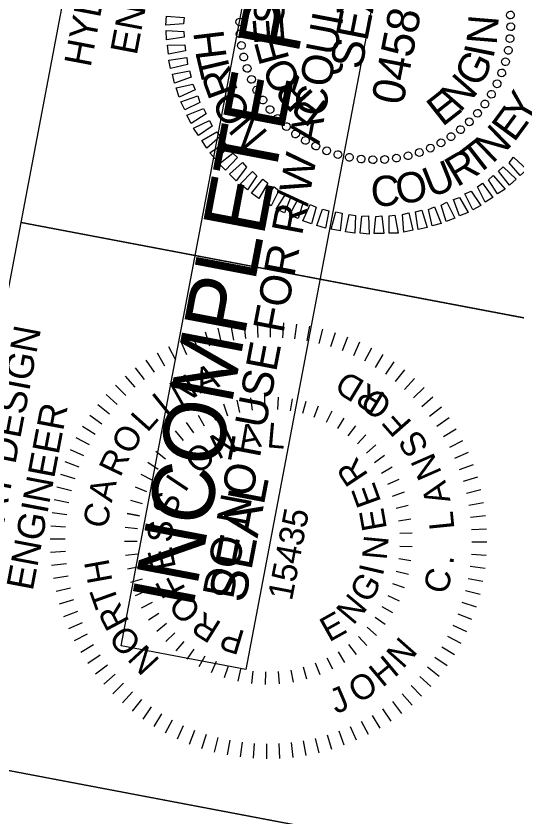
# Model space of a CAD drawing. Extents: x 1615685 to 1617075, y 899072 to 901363.
# Drawn here: x 1616035.7 to 1616128.3, y 900930.9 to 901079 of the extents above; entities that cross this region are included whole.
import ezdxf

# ---------------------------------------------------------------- set-up
doc = ezdxf.new("R2010")
doc.units = 0
for name, color, linetype in [('Default', 7, 'Continuous'), ('Exist Structure Minor Pipes RCP 15 Inch Text', 7, 'Continuous'), ('Prop Plan Preparation Crest Label', 7, 'Continuous'), ('Scratch_Level_8', 7, 'Continuous')]:
    doc.layers.add(name, color=color, linetype=linetype)

msp = doc.modelspace()

# ---------------------------------------------------------------- linework, layer by layer
at = {"layer": 'Default'}
for p, q in [((1616077.12, 901077.93), (1616077.12, 901077.93)), ((1616127.23, 901077.04), (1616127.23, 901077.04)), ((1616077.15, 901075.73), (1616077.15, 901075.73)), ((1616127.05, 901074.83), (1616127.05, 901074.83)), ((1616077.39, 901073.55), (1616077.39, 901073.55)), ((1616126.78, 901072.64), (1616126.78, 901072.64)), ((1616077.85, 901071.47), (1616077.85, 901071.47)), ((1616078.46, 901069.37), (1616078.46, 901069.37)), ((1616126.27, 901070.55), (1616126.27, 901070.55)), ((1616125.56, 901068.5), (1616125.56, 901068.5)), ((1616079.29, 901067.32), (1616079.29, 901067.32)), ((1616124.71, 901066.47), (1616124.71, 901066.47)), ((1616080.17, 901065.32), (1616080.17, 901065.32)), ((1616081.38, 901063.45), (1616081.38, 901063.45)), ((1616123.67, 901064.53), (1616123.67, 901064.53)), ((1616122.46, 901062.73), (1616122.46, 901062.73)), ((1616082.62, 901061.68), (1616082.62, 901061.68)), ((1616121.1, 901061.01), (1616121.1, 901061.01)), ((1616084.14, 901060.06), (1616084.14, 901060.06)), ((1616119.57, 901059.43), (1616119.57, 901059.43)), ((1616085.72, 901058.53), (1616085.72, 901058.53)), ((1616117.96, 901057.96), (1616117.96, 901057.96)), ((1616087.45, 901057.17), (1616087.45, 901057.17)), ((1616089.25, 901055.96), (1616089.25, 901055.96)), ((1616116.18, 901056.67), (1616116.18, 901056.67)), ((1616091.13, 901054.93), (1616091.13, 901054.93)), ((1616112.37, 901054.61), (1616112.37, 901054.61)), ((1616114.32, 901055.51), (1616114.32, 901055.51)), ((1616093.16, 901054.08), (1616093.16, 901054.08)), ((1616095.21, 901053.37), (1616095.21, 901053.37)), ((1616108.22, 901053.18), (1616108.22, 901053.18)), ((1616110.32, 901053.79), (1616110.32, 901053.79)), ((1616097.35, 901052.85), (1616097.35, 901052.85)), ((1616099.54, 901052.58), (1616099.54, 901052.58)), ((1616101.71, 901052.46), (1616101.71, 901052.46)), ((1616103.9, 901052.49), (1616103.9, 901052.49)), ((1616106.09, 901052.73), (1616106.09, 901052.73))]:
    msp.add_line(p, q, dxfattribs=at)
for points in [[(1616066.66, 901077.57), (1616063.41, 901077.34), (1616063.53, 901079), (1616066.79, 901078.77)], [(1616066.79, 901075.1), (1616063.49, 901074.63), (1616063.47, 901076.36), (1616066.75, 901076.18)], [(1616067.02, 901072.61), (1616063.9, 901072), (1616063.7, 901073.62), (1616066.88, 901073.71)], [(1616067.4, 901070.1), (1616064.29, 901069.33), (1616063.98, 901070.86), (1616067.28, 901071.34)], [(1616068.06, 901067.73), (1616064.99, 901066.64), (1616064.6, 901068.3), (1616067.78, 901068.9)], [(1616068.82, 901065.39), (1616065.86, 901064.03), (1616065.33, 901065.76), (1616068.42, 901066.43)], [(1616069.69, 901063.03), (1616066.88, 901061.69), (1616066.15, 901063.16), (1616069.32, 901064.27)], [(1616070.86, 901060.92), (1616068.07, 901059.17), (1616067.3, 901060.69), (1616070.34, 901061.93)], [(1616071.99, 901058.66), (1616069.46, 901056.91), (1616068.52, 901058.31), (1616071.49, 901059.72)], [(1616073.46, 901056.74), (1616071, 901054.62), (1616070.06, 901056.03), (1616072.81, 901057.63)], [(1616075, 901054.71), (1616072.62, 901052.47), (1616071.55, 901053.75), (1616074.25, 901055.57)], [(1616076.62, 901052.86), (1616074.44, 901050.54), (1616073.24, 901051.69), (1616075.81, 901053.68)], [(1616078.31, 901051.06), (1616076.4, 901048.58), (1616075.16, 901049.79), (1616077.57, 901051.97)], [(1616127.67, 901052.91), (1616130.14, 901050.64), (1616128.91, 901049.56), (1616126.86, 901051.89)], [(1616080.24, 901049.46), (1616078.47, 901046.9), (1616077.14, 901047.92), (1616079.43, 901050.28)], [(1616125.8, 901051.13), (1616128.16, 901048.89), (1616126.92, 901047.75), (1616124.93, 901050.33)], [(1616082.28, 901048.15), (1616080.6, 901045.31), (1616079.26, 901046.29), (1616081.34, 901048.84)], [(1616123.91, 901049.56), (1616126.12, 901047.04), (1616124.73, 901046.14), (1616123.09, 901048.75)], [(1616084.3, 901046.78), (1616082.88, 901043.9), (1616081.51, 901044.73), (1616083.42, 901047.47)], [(1616121.95, 901048.11), (1616123.89, 901045.49), (1616122.44, 901044.6), (1616121, 901047.43)], [(1616086.51, 901045.59), (1616085.33, 901042.66), (1616083.83, 901043.31), (1616085.6, 901046.12)], [(1616119.83, 901046.64), (1616121.66, 901043.99), (1616120.18, 901043.21), (1616118.71, 901046.14)], [(1616088.81, 901044.58), (1616087.87, 901041.56), (1616086.26, 901042.18), (1616087.79, 901045.09)], [(1616091.19, 901043.71), (1616090.33, 901040.62), (1616088.7, 901041.14), (1616090.06, 901044.19)], [(1616115.36, 901044.61), (1616116.82, 901041.67), (1616115.22, 901041.02), (1616114.33, 901044.04)], [(1616117.67, 901045.48), (1616119.32, 901042.71), (1616117.72, 901042.11), (1616116.62, 901045.07)], [(1616093.55, 901043), (1616092.93, 901039.81), (1616091.29, 901040.28), (1616092.34, 901043.33)], [(1616096.01, 901042.57), (1616095.64, 901039.33), (1616093.96, 901039.61), (1616094.83, 901042.8)], [(1616108.35, 901042.61), (1616109.1, 901039.41), (1616107.4, 901039.08), (1616107.17, 901042.33)], [(1616110.74, 901043.11), (1616111.7, 901039.92), (1616110.05, 901039.58), (1616109.56, 901042.83)], [(1616113.05, 901043.73), (1616114.29, 901040.69), (1616112.62, 901040.25), (1616111.99, 901043.28)], [(1616098.48, 901042.14), (1616098.35, 901038.9), (1616096.62, 901039.14), (1616097.29, 901042.32)], [(1616100.86, 901042.08), (1616101.01, 901038.69), (1616099.32, 901038.87), (1616099.67, 901042.01)], [(1616103.31, 901042.11), (1616103.69, 901038.83), (1616101.95, 901038.81), (1616102.21, 901041.97)], [(1616105.77, 901042.2), (1616106.35, 901038.87), (1616104.67, 901038.89), (1616104.67, 901042.05)]]:
    msp.add_lwpolyline(points, close=True, dxfattribs=at)
for centre, major_axis in [((1616127.12, 901079.23), (0.718, 0.05)), ((1616077.08, 901077.94), (-0.719, 0.013)), ((1616127.18, 901077.05), (0.719, -0.013)), ((1616077.13, 901075.76), (-0.718, -0.05)), ((1616127.04, 901074.87), (0.715, -0.075)), ((1616077.38, 901073.59), (-0.71, -0.112)), ((1616077.81, 901071.44), (-0.698, -0.174)), ((1616126.72, 901072.71), (0.706, -0.138)), ((1616126.21, 901070.58), (0.691, -0.199)), ((1616078.43, 901069.35), (-0.68, -0.234)), ((1616125.51, 901068.51), (0.671, -0.258)), ((1616079.23, 901067.31), (-0.657, -0.292)), ((1616124.64, 901066.5), (0.646, -0.316)), ((1616080.21, 901065.36), (-0.629, -0.348)), ((1616123.6, 901064.58), (0.616, -0.371)), ((1616081.35, 901063.49), (-0.596, -0.402)), ((1616122.39, 901062.76), (0.582, -0.423)), ((1616082.65, 901061.74), (-0.559, -0.452)), ((1616121.03, 901061.05), (0.543, -0.472)), ((1616084.1, 901060.1), (-0.518, -0.499)), ((1616085.68, 901058.59), (-0.472, -0.543)), ((1616119.52, 901059.47), (0.499, -0.518)), ((1616087.39, 901057.23), (-0.423, -0.582)), ((1616116.13, 901056.72), (0.402, -0.596)), ((1616117.89, 901058.02), (0.452, -0.559)), ((1616089.21, 901056.02), (-0.371, -0.616)), ((1616114.27, 901055.58), (0.348, -0.629)), ((1616091.13, 901054.98), (-0.316, -0.646)), ((1616093.14, 901054.11), (-0.258, -0.671)), ((1616110.27, 901053.8), (0.234, -0.68)), ((1616112.31, 901054.6), (0.292, -0.657)), ((1616095.21, 901053.41), (-0.199, -0.691)), ((1616097.34, 901052.9), (-0.138, -0.706)), ((1616099.5, 901052.58), (-0.075, -0.715)), ((1616101.68, 901052.45), (-0.013, -0.719)), ((1616103.86, 901052.5), (0.05, -0.718)), ((1616106.04, 901052.75), (0.112, -0.71)), ((1616108.18, 901053.18), (0.174, -0.698))]:
    msp.add_ellipse(centre, major_axis=major_axis, ratio=0.999708, dxfattribs=at)
at = {"layer": 'Exist Structure Minor Pipes RCP 15 Inch Text'}
msp.add_lwpolyline([(1616078.19, 900958.16), (1616055.11, 900962.54), (1616082.53, 901106.96), (1616105.61, 901102.58)], close=True, dxfattribs=at)
at = {"layer": 'Prop Plan Preparation Crest Label'}
for p, q in [((1616077.83, 901022.13), (1616078.14, 901019.39)), ((1616080.26, 901022.33), (1616080.4, 901019.58)), ((1616082.7, 901022.38), (1616082.67, 901019.63)), ((1616085.13, 901022.29), (1616084.94, 901019.54)), ((1616087.56, 901022.05), (1616087.2, 901019.32)), ((1616070.67, 901020.65), (1616071.47, 901018.01)), ((1616073.03, 901021.28), (1616073.66, 901018.61)), ((1616075.42, 901021.78), (1616075.89, 901019.07)), ((1616089.97, 901021.66), (1616089.45, 901018.96)), ((1616092.35, 901021.13), (1616091.67, 901018.47)), ((1616094.69, 901020.46), (1616093.85, 901017.84)), ((1616066.1, 901018.95), (1616067.21, 901016.44)), ((1616068.36, 901019.87), (1616069.32, 901017.29)), ((1616096.99, 901019.65), (1616096, 901017.08)), ((1616063.9, 901017.9), (1616065.16, 901015.46)), ((1616099.23, 901018.7), (1616098.09, 901016.2)), ((1616101.42, 901017.61), (1616100.12, 901015.18)), ((1616061.77, 901016.72), (1616063.17, 901014.36)), ((1616103.53, 901016.4), (1616102.09, 901014.05)), ((1616059.71, 901015.41), (1616061.26, 901013.14)), ((1616105.57, 901015.05), (1616103.99, 901012.8)), ((1616057.74, 901013.98), (1616059.41, 901011.81)), ((1616107.52, 901013.6), (1616105.81, 901011.44)), ((1616055.85, 901012.44), (1616057.66, 901010.36)), ((1616109.39, 901012.02), (1616107.54, 901009.98)), ((1616054.06, 901010.78), (1616055.99, 901008.82)), ((1616111.15, 901010.34), (1616109.19, 901008.41)), ((1616052.38, 901009.02), (1616054.42, 901007.18)), ((1616081.62, 901008.61), (1616081.69, 901006.32)), ((1616084.2, 901008.56), (1616084.04, 901006.27)), ((1616112.8, 901008.55), (1616110.73, 901006.74)), ((1616050.8, 901007.16), (1616052.95, 901005.44)), ((1616074.05, 901007.28), (1616074.77, 901005.1)), ((1616076.53, 901007.97), (1616077.03, 901005.73)), ((1616079.06, 901008.41), (1616079.35, 901006.13)), ((1616086.75, 901008.26), (1616086.37, 901006)), ((1616089.26, 901007.72), (1616088.67, 901005.5)), ((1616071.65, 901006.36), (1616072.58, 901004.26)), ((1616090.83, 901004.81), (1616091.63, 901006.96)), ((1616094.07, 901005.92), (1616093.07, 901003.86)), ((1616114.35, 901006.66), (1616112.17, 901004.98)), ((1616049.34, 901005.2), (1616051.59, 901003.62)), ((1616069.35, 901005.21), (1616070.47, 901003.21)), ((1616096.32, 901004.67), (1616095.12, 901002.72)), ((1616115.78, 901004.69), (1616113.5, 901003.14)), ((1616048, 901003.17), (1616050.34, 901001.72)), ((1616067.18, 901003.84), (1616068.49, 901001.96)), ((1616098.44, 901003.22), (1616097.06, 901001.4)), ((1616117.09, 901002.63), (1616114.72, 901001.22)), ((1616065.14, 901002.28), (1616066.63, 901000.53)), ((1616100.41, 901001.58), (1616098.86, 900999.89)), ((1616046.78, 901001.05), (1616049.22, 900999.76)), ((1616063.26, 901000.52), (1616064.91, 900998.92)), ((1616102.22, 900999.74), (1616100.51, 900998.21)), ((1616118.27, 901000.49), (1616115.83, 900999.24)), ((1616045.7, 900998.87), (1616048.2, 900997.72)), ((1616061.57, 900998.58), (1616063.36, 900997.16)), ((1616119.32, 900998.3), (1616116.8, 900997.19)), ((1616103.84, 900997.74), (1616101.99, 900996.39)), ((1616044.75, 900996.62), (1616047.31, 900995.63)), ((1616060.06, 900996.5), (1616061.99, 900995.25)), ((1616105.26, 900995.6), (1616103.28, 900994.43)), ((1616120.24, 900996.04), (1616117.66, 900995.08)), ((1616043.94, 900994.32), (1616046.56, 900993.49)), ((1616058.77, 900994.28), (1616060.81, 900993.22)), ((1616121.02, 900993.72), (1616118.38, 900992.93)), ((1616106.46, 900993.33), (1616104.39, 900992.36)), ((1616043.27, 900991.98), (1616045.93, 900991.3)), ((1616057.7, 900991.94), (1616059.83, 900991.09)), ((1616107.44, 900990.95), (1616105.28, 900990.18)), ((1616121.65, 900991.37), (1616118.97, 900990.73)), ((1616042.73, 900989.6), (1616045.44, 900989.08)), ((1616056.86, 900989.51), (1616059.05, 900988.87)), ((1616108.18, 900988.49), (1616105.96, 900987.93)), ((1616122.15, 900988.98), (1616119.43, 900988.5)), ((1616042.35, 900987.19), (1616045.08, 900986.84)), ((1616056.25, 900987.01), (1616058.5, 900986.58)), ((1616058.5, 900986.58), (1616056.25, 900987.01)), ((1616122.49, 900986.57), (1616119.76, 900986.26)), ((1616108.69, 900985.97), (1616106.42, 900985.63)), ((1616042.11, 900984.76), (1616044.85, 900984.58)), ((1616055.89, 900984.47), (1616058.17, 900984.26)), ((1616108.95, 900983.41), (1616106.66, 900983.29)), ((1616122.69, 900984.14), (1616119.95, 900984)), ((1616042.01, 900982.33), (1616044.77, 900982.31)), ((1616055.78, 900981.9), (1616058.07, 900981.91)), ((1616108.96, 900980.84), (1616106.67, 900980.94)), ((1616122.75, 900981.7), (1616120, 900981.72)), ((1616042.07, 900979.89), (1616044.82, 900980.03)), ((1616055.91, 900979.33), (1616058.19, 900979.56)), ((1616122.65, 900979.26), (1616119.91, 900979.45)), ((1616042.27, 900977.46), (1616045.01, 900977.77)), ((1616108.73, 900978.28), (1616106.46, 900978.61)), ((1616056.29, 900976.79), (1616058.54, 900977.24)), ((1616108.24, 900975.76), (1616106.01, 900976.3)), ((1616122.42, 900976.84), (1616119.69, 900977.19)), ((1616042.62, 900975.05), (1616045.33, 900975.52)), ((1616056.92, 900974.3), (1616059.11, 900974.96)), ((1616122.03, 900974.43), (1616119.33, 900974.95)), ((1616043.12, 900972.66), (1616045.79, 900973.3)), ((1616107.52, 900973.29), (1616105.35, 900974.04)), ((1616057.78, 900971.88), (1616059.91, 900972.75)), ((1616104.47, 900971.85), (1616106.55, 900970.89)), ((1616121.5, 900972.05), (1616118.83, 900972.73)), ((1616043.75, 900970.31), (1616046.38, 900971.1)), ((1616058.88, 900969.55), (1616060.91, 900970.62)), ((1616120.83, 900969.71), (1616118.21, 900970.54)), ((1616044.53, 900967.99), (1616047.11, 900968.95)), ((1616060.19, 900967.34), (1616062.11, 900968.61)), ((1616105.37, 900968.63), (1616103.39, 900969.78)), ((1616103.97, 900966.47), (1616102.11, 900967.81)), ((1616120.01, 900967.41), (1616117.45, 900968.4)), ((1616045.44, 900965.73), (1616047.96, 900966.84)), ((1616061.71, 900965.27), (1616063.49, 900966.71)), ((1616102.37, 900964.46), (1616100.65, 900965.97)), ((1616119.06, 900965.16), (1616116.56, 900966.31)), ((1616046.49, 900963.54), (1616048.94, 900964.79)), ((1616063.42, 900963.35), (1616065.06, 900964.96)), ((1616100.58, 900962.61), (1616099.02, 900964.28)), ((1616117.98, 900962.97), (1616115.55, 900964.27)), ((1616047.68, 900961.4), (1616050.04, 900962.81)), ((1616065.31, 900961.61), (1616066.79, 900963.36)), ((1616098.63, 900960.94), (1616097.23, 900962.76)), ((1616067.36, 900960.05), (1616068.66, 900961.95)), ((1616096.52, 900959.48), (1616095.3, 900961.42)), ((1616116.77, 900960.86), (1616114.42, 900962.31)), ((1616048.98, 900959.34), (1616051.26, 900960.89)), ((1616069.55, 900958.71), (1616070.66, 900960.72)), ((1616071.86, 900957.58), (1616072.77, 900959.68)), ((1616094.28, 900958.21), (1616093.25, 900960.27)), ((1616115.42, 900958.83), (1616113.17, 900960.4)), ((1616050.41, 900957.37), (1616052.59, 900959.05)), ((1616074.27, 900956.68), (1616074.97, 900958.86)), ((1616076.75, 900956.01), (1616077.24, 900958.25)), ((1616089.48, 900956.38), (1616088.87, 900958.58)), ((1616091.92, 900957.18), (1616091.1, 900959.32)), ((1616113.97, 900956.87), (1616111.81, 900958.59)), ((1616051.96, 900955.48), (1616054.03, 900957.29)), ((1616079.29, 900955.59), (1616079.56, 900957.86)), ((1616081.85, 900955.42), (1616081.9, 900957.71)), ((1616084.43, 900955.49), (1616084.25, 900957.77)), ((1616086.98, 900955.81), (1616086.58, 900958.07)), ((1616112.39, 900955.01), (1616110.34, 900956.85)), ((1616053.62, 900953.69), (1616055.58, 900955.62)), ((1616110.7, 900953.25), (1616108.77, 900955.21)), ((1616055.38, 900952.01), (1616057.22, 900954.05)), ((1616057.24, 900950.43), (1616058.95, 900952.59)), ((1616107.03, 900950.04), (1616105.35, 900952.22)), ((1616108.92, 900951.59), (1616107.11, 900953.66)), ((1616059.2, 900948.97), (1616060.77, 900951.23)), ((1616105.05, 900948.62), (1616103.51, 900950.89)), ((1616061.23, 900947.63), (1616062.67, 900949.98)), ((1616103, 900947.31), (1616101.59, 900949.67)), ((1616063.34, 900946.42), (1616064.64, 900948.85)), ((1616065.53, 900945.33), (1616066.67, 900947.83)), ((1616100.86, 900946.13), (1616099.6, 900948.57)), ((1616067.77, 900944.38), (1616068.77, 900946.95)), ((1616096.4, 900944.16), (1616095.45, 900946.74)), ((1616098.66, 900945.08), (1616097.55, 900947.59)), ((1616070.07, 900943.57), (1616070.91, 900946.19)), ((1616072.42, 900942.9), (1616073.09, 900945.56)), ((1616074.8, 900942.37), (1616075.31, 900945.07)), ((1616089.35, 900942.25), (1616088.87, 900944.96)), ((1616091.74, 900942.75), (1616091.1, 900945.42)), ((1616094.09, 900943.38), (1616093.29, 900946.02)), ((1616077.21, 900941.98), (1616077.56, 900944.71)), ((1616079.63, 900941.74), (1616079.82, 900944.48)), ((1616082.07, 900941.65), (1616082.09, 900944.4)), ((1616084.5, 900941.7), (1616084.36, 900944.45)), ((1616086.94, 900941.9), (1616086.63, 900944.64))]:
    msp.add_line(p, q, dxfattribs=at)
at = {"layer": 'Scratch_Level_8'}
msp.add_line((1616036.64, 901040.86), (1616147.13, 901019.89), dxfattribs=at)
for points in [[(1616036.64, 901040.86), (1616055.28, 901139.09), (1616165.82, 901118.12), (1616147.18, 901019.87)], [(1616770.16, 899476.57), (1615738.61, 899672.4), (1615981.06, 900949.58), (1616128.49, 900921.6), (1616165.82, 901118.12), (1617049.96, 900950.25)], [(1616017.98, 900942.57), (1616036.64, 901040.86), (1616147.18, 901019.87), (1616128.49, 900921.6)]]:
    msp.add_lwpolyline(points, close=True, dxfattribs=at)

# ---------------------------------------------------------------- texts
at = {"layer": 'Default'}
for s, height, rotation, p in [('SEAL', 5.992, 78.9784, (1616099.61, 901068.97)), ('045893', 5.994, 78.9784, (1616107.24, 901062.37)), ('S', 5.6, 84.0272, (1616085.04, 901077.2)), ('E', 5.6, 94.6313, (1616085.39, 901074.05)), ('N', 5.6, 85.3078, (1616124.55, 901073.58)), ('H', 5.6, 96.9052, (1616074.66, 901071.36)), ('F', 5.6, 105.1249, (1616086.3, 901071.05)), ('G', 5.6, 63.7309, (1616121.53, 901065.63)), ('I', 5.6, 78.6468, (1616123.94, 901071.01)), ('T', 5.6, 103.3059, (1616075.52, 901068.33)), ('O', 5.6, 121.0358, (1616088.68, 901066.95)), ('R', 5.6, 110.2513, (1616076.83, 901065.17)), ('R', 5.6, 132.0822, (1616090.96, 901064.56)), ('N', 5.6, 48.8151, (1616117.82, 901061.05)), ('E', 5.6, 38.2109, (1616114.53, 901058.45)), ('Y', 5.6, 60.315, (1616130.17, 901058.64)), ('O', 5.6, 120.4651, (1616079.42, 901060.87)), ('P', 5.6, 142.6864, (1616093.53, 901062.71)), ('E', 5.6, 53.6667, (1616127.79, 901055.53)), ('N', 5.6, 130.0104, (1616082.49, 901057.33)), ('N', 5.6, 44.1214, (1616123.79, 901051.59)), ('T', 5.6, 37.7208, (1616120.77, 901049.34)), ('R', 5.6, 30.7754, (1616117.23, 901047.3)), ('U', 5.6, 21.8615, (1616112.36, 901045.33)), ('O', 5.6, 11.6476, (1616106.49, 901044.04)), ('C', 5.6, 3.0185, (1616101.42, 901043.77))]:
    msp.add_text(s, height=height, rotation=rotation, dxfattribs=at).set_placement(p)
at = {"layer": 'Exist Structure Minor Pipes RCP 15 Inch Text'}
for s, height, p in [('INCOMPLETE PLANS', 11.52, (1616068.37, 900969.13)), ('DO NOT USE FOR R/W ACQUISITION', 5.76, (1616075.8, 900971.03))]:
    msp.add_text(s, height=height, rotation=79.2494, dxfattribs=at).set_placement(p)
at = {"layer": 'Prop Plan Preparation Crest Label'}
for s, height, rotation, p in [('A', 4.58, 19.6866, (1616069.73, 901009.19)), ('N', 4.58, 29.4542, (1616065.84, 901006.85)), (' RD', 4.582, 148.842, (1616105.68, 901008.17)), ('I', 4.58, 38.7486, (1616063.29, 901005)), ('O ', 4.582, 140.1692, (1616105.58, 901007.52)), ('L', 4.58, 48.3241, (1616059.98, 901001.88)), ('F', 4.58, 131.3766, (1616109.08, 901003.81)), ('O', 4.58, 61.4604, (1616057.1, 900997.68)), ('N', 4.58, 25.6327, (1616073.06, 900996.93)), ('A', 4.58, 10.3364, (1616077.21, 900998.69)), ('L', 4.58, 355.0402, (1616081.95, 900999.29)), ('S', 4.58, 122.494, (1616112.19, 900999.33)), ('O', 4.58, 40.9289, (1616069.38, 900994.03)), ('R', 4.58, 64.5172, (1616054.97, 900993.57)), ('R', 4.58, 123.7344, (1616100.95, 900994.09)), ('N', 4.58, 113.6113, (1616114.5, 900994.52)), ('I', 4.58, 56.2252, (1616066.93, 900990.74)), ('A', 4.58, 76.5265, (1616053.39, 900988.93)), ('SEAL', 6.878, 79.1695, (1616078.04, 900970.3)), ('E', 4.58, 109.9633, (1616103.27, 900989.2)), ('A', 4.58, 104.7887, (1616116.06, 900989.37)), ('S', 4.58, 71.5214, (1616065.04, 900986.14)), ('C', 4.58, 76.5265, (1616052.36, 900984.02)), ('15435', 4.582, 79.1695, (1616086.71, 900970.74)), ('E', 4.58, 99.9775, (1616104.3, 900984.22)), ('L', 4.58, 95.7861, (1616116.78, 900984.19)), ('S', 4.58, 86.8177, (1616064.56, 900981.58)), ('N', 4.58, 84.5854, (1616104.22, 900978.32)), ('E', 4.58, 102.1139, (1616065.3, 900977.05)), ('H', 4.58, 100.2372, (1616053.54, 900974.52)), ('I', 4.58, 76.9557, (1616103.48, 900975.3)), ('.', 4.58, 83.0018, (1616116.52, 900977.46)), ('C', 4.58, 75.2595, (1616115.33, 900971.89)), ('F', 4.58, 117.4101, (1616067.15, 900972.96)), ('G', 4.58, 58.8609, (1616101.02, 900970.21)), ('T', 4.58, 109.6691, (1616054.81, 900970.52)), ('O', 4.58, 132.7064, (1616070.21, 900969.28)), ('N', 4.58, 50.0947, (1616098.06, 900966.21)), ('R', 4.58, 117.8301, (1616056.75, 900967.01)), ('R', 4.58, 148.0026, (1616073.91, 900966.72)), ('E', 4.58, 29.2396, (1616093.59, 900963.15)), ('O', 4.58, 130.8868, (1616059.16, 900963.17)), ('P', 4.58, 163.2989, (1616078.24, 900965.19)), ('N', 4.58, 48.4917, (1616107.24, 900958.13)), ('N', 4.58, 132.8463, (1616062.46, 900959.86)), ('H', 4.58, 39.8191, (1616103.44, 900954.72)), ('O', 4.58, 31.1764, (1616098.94, 900951.78)), ('J', 4.58, 23.1045, (1616094.87, 900949.89))]:
    msp.add_text(s, height=height, rotation=rotation, dxfattribs=at).set_placement(p)
at = {"layer": 'Scratch_Level_8'}
for s, height, p in [('HYDRAULICS', 5, (1616049.47, 901069.43)), ('ENGINEER', 5, (1616058, 901071.64)), ('ROADWAY DESIGN', 5.0001, (1616028.77, 900960.24)), ('ENGINEER', 5, (1616038.78, 900972.58))]:
    msp.add_text(s, height=height, rotation=79.2494, dxfattribs=at).set_placement(p)

doc.saveas('drawing.dxf')
